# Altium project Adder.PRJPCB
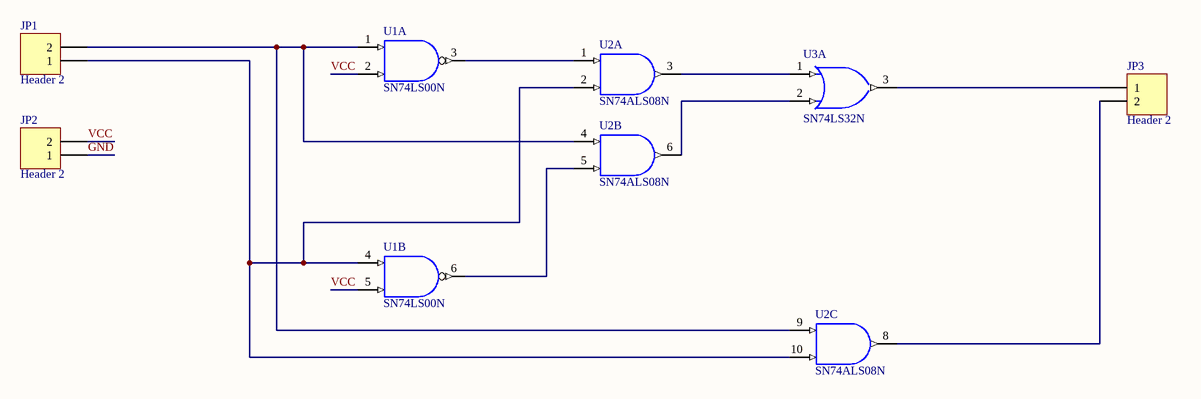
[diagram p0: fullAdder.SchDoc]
1 sheet, 6 parts. Net scope: global (net labels, ports and power ports of the same name join across sheets).
Board file: Adder.PCBDOC

## Sheet fullAdder.SchDoc
size B

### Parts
JP1  Header 2  [HDR1X2]
JP2  Header 2  [HDR1X2]
JP3  Header 2  [HDR1X2]
U1  SN74LS00N  [DIP-14/D19.7]  (parts A,B of 4)
U2  SN74ALS08N  [DIP-14/D19.7]  (parts A,B,C of 4)
U3  SN74LS32N  [DIP-14/D19.7]  (part A of 4)

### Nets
GND: JP2.1 U1.7(GND) U2.7(GND) U3.7(GND)
VCC: JP2.2 U1.2(B) U1.5(B) U1.14(VCC) U2.14(VCC) U3.14(VCC)
NetJP1_1: JP1.1 U1.4(A) U2.2(B) U2.10(B)
NetJP1_2: JP1.2 U1.1(A) U2.4(A) U2.9(A)
NetJP3_1: JP3.1 U3.3(Y)
NetJP3_2: JP3.2 U2.8(Y)
NetU1_3: U1.3(Y) U2.1(A)
NetU1_6: U1.6(Y) U2.5(B)
NetU2_3: U2.3(Y) U3.1(A)
NetU2_6: U2.6(Y) U3.2(B)

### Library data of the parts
JP1-JP3 = Header 2: Header, 2-Pin; Manufacturer: Generic Components; Class I: Connector
U1 = SN74LS00N: Quadruple 2-Input Positive-NAND Gate; Manufacturer: Texas Instruments; Class I: Logic
U2 = SN74ALS08N: Quadruple 2-Input Positive-AND Gate; Manufacturer: Texas Instruments; Class I: Logic
U3 = SN74LS32N: Quadruple 2-Input Positive-OR Gate; Manufacturer: Texas Instruments; Class I: Logic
